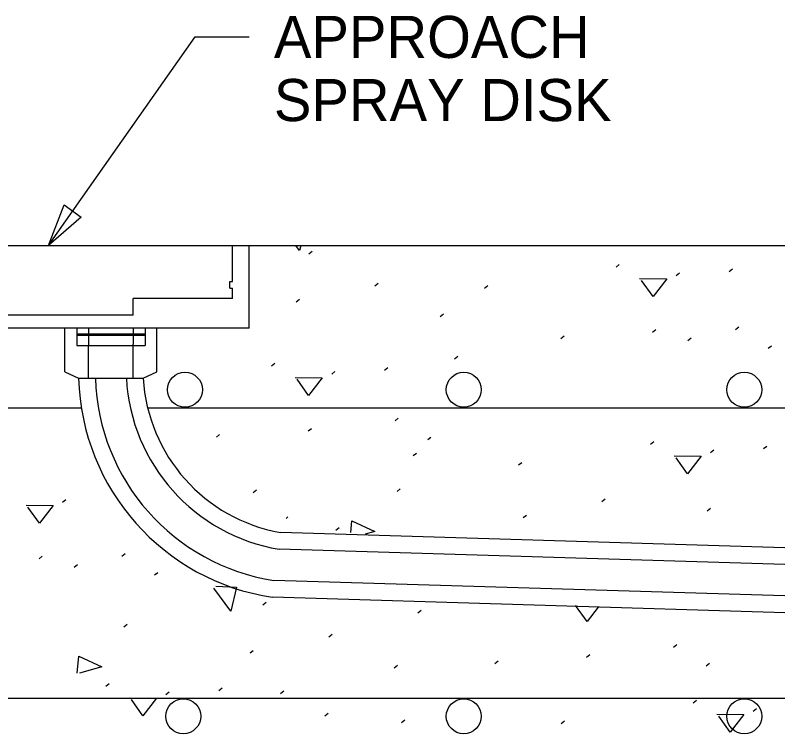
# Model space of a CAD drawing. Extents: x 3239 to 4230, y -4276 to -2494.
# Drawn here: x 3415.4 to 3469.7, y -3229.6 to -3178.4 of the extents above; entities that cross this region are included whole.
import ezdxf

# ---------------------------------------------------------------- set-up
doc = ezdxf.new("R2010")
doc.units = 0
doc.layers.add('2', color=7, linetype='Continuous')

msp = doc.modelspace()

# ---------------------------------------------------------------- linework, layer by layer
at = {"layer": '2'}
for p, q in [((3407.277, -3194.76), (3615.577, -3194.76)), ((3430.835, -3197.339), (3430.835, -3194.76)), ((3432.032, -3200.655), (3432.032, -3194.76)), ((3432.032, -3200.655), (3432.032, -3194.76)), ((3436.289, -3195.36), (3436.522, -3195.174)), ((3458.192, -3196.302), (3458.425, -3196.116)), ((3462.48, -3196.893), (3462.713, -3196.707)), ((3466.254, -3196.614), (3466.487, -3196.427)), ((3430.651, -3197.8), (3430.651, -3197.339)), ((3430.651, -3197.339), (3430.835, -3197.339)), ((3430.651, -3197.8), (3430.835, -3197.8)), ((3430.835, -3198.536), (3430.835, -3197.8)), ((3440.995, -3197.643), (3441.228, -3197.457)), ((3448.815, -3197.813), (3449.048, -3197.627)), ((3430.835, -3198.536), (3423.769, -3198.536)), ((3423.769, -3199.734), (3423.769, -3198.536)), ((3435.38, -3198.785), (3435.613, -3198.598)), ((3423.769, -3199.734), (3413.059, -3199.734)), ((3445.655, -3199.833), (3445.888, -3199.647)), ((3466.717, -3200.758), (3466.95, -3200.572)), ((3420.584, -3200.655), (3403.94, -3200.655)), ((3418.893, -3203.771), (3418.893, -3200.655)), ((3419.737, -3200.655), (3419.737, -3201.898)), ((3419.737, -3201.069), (3424.615, -3201.069)), ((3419.737, -3201.161), (3424.615, -3201.161)), ((3432.032, -3200.655), (3420.584, -3200.655)), ((3420.584, -3200.655), (3420.584, -3201.069)), ((3420.584, -3201.161), (3420.584, -3201.898)), ((3423.769, -3200.655), (3423.769, -3201.069)), ((3423.769, -3201.161), (3423.769, -3201.791)), ((3424.615, -3200.655), (3424.615, -3201.898)), ((3425.459, -3203.771), (3425.459, -3200.655)), ((3460.802, -3200.947), (3461.035, -3200.761)), ((3454.256, -3201.39), (3454.489, -3201.203)), ((3463.307, -3201.531), (3463.54, -3201.345)), ((3419.737, -3201.898), (3424.615, -3201.898)), ((3420.584, -3204.232), (3420.584, -3201.898)), ((3423.769, -3204.232), (3423.769, -3201.791)), ((3469.044, -3202.095), (3469.277, -3201.909)), ((3446.677, -3202.841), (3446.91, -3202.655)), ((3433.632, -3203.342), (3433.865, -3203.156)), ((3418.893, -3203.771), (3419.876, -3204.232)), ((3424.478, -3204.232), (3425.459, -3203.771)), ((3437.92, -3203.934), (3438.153, -3203.747)), ((3441.694, -3203.654), (3441.927, -3203.468)), ((3419.876, -3204.232), (3424.478, -3204.232)), ((3381.4, -3206.332), (3420.07, -3206.332)), ((3424.793, -3206.332), (3613.332, -3206.332)), ((3442.437, -3207.268), (3442.67, -3207.081)), ((3429.695, -3208.43), (3429.928, -3208.244)), ((3436.242, -3207.987), (3436.475, -3207.801)), ((3444.763, -3208.605), (3444.996, -3208.419)), ((3460.651, -3208.935), (3460.884, -3208.749)), ((3464.939, -3209.527), (3465.172, -3209.34)), ((3468.713, -3209.247), (3468.946, -3209.061)), ((3443.734, -3209.746), (3443.967, -3209.559)), ((3451.24, -3210.412), (3451.473, -3210.225)), ((3432.328, -3212.367), (3432.561, -3212.181)), ((3442.577, -3212.3), (3442.81, -3212.114)), ((3418.726, -3213.052), (3418.959, -3212.866)), ((3457.185, -3213.022), (3457.418, -3212.836)), ((3464.691, -3213.688), (3464.924, -3213.502)), ((3434.665, -3214.221), (3434.795, -3214.117)), ((3451.57, -3214.164), (3451.803, -3213.978)), ((3679.628, -3222.686), (3434.263, -3215.224)), ((3438.225, -3215.049), (3438.458, -3214.863)), ((3417.049, -3217.106), (3417.282, -3216.92)), ((3422.964, -3216.917), (3423.197, -3216.731)), ((3700.705, -3224.527), (3434.165, -3216.422)), ((3419.553, -3217.69), (3419.786, -3217.504)), ((3425.29, -3218.254), (3425.523, -3218.068)), ((3700.637, -3226.756), (3433.794, -3218.642)), ((3433.006, -3220.388), (3433.238, -3220.202)), ((3679.628, -3227.318), (3433.701, -3219.839)), ((3444.072, -3220.943), (3444.305, -3220.757)), ((3423.104, -3221.949), (3423.337, -3221.763)), ((3437.712, -3222.672), (3437.945, -3222.485)), ((3462.289, -3223.392), (3462.522, -3223.206)), ((3432.097, -3223.813), (3432.33, -3223.627)), ((3456.094, -3224.112), (3456.327, -3223.926)), ((3449.547, -3224.555), (3449.78, -3224.368)), ((3464.615, -3224.729), (3464.848, -3224.543)), ((3442.371, -3224.862), (3442.604, -3224.675)), ((3421.811, -3226.179), (3422.044, -3225.992)), ((3426.099, -3226.77), (3426.332, -3226.583)), ((3429.873, -3226.49), (3430.106, -3226.304)), ((3434.263, -3226.704), (3434.496, -3226.518)), ((3380.058, -3227.042), (3612.771, -3227.042)), ((3463.69, -3227.36), (3463.923, -3227.174)), ((3467.978, -3227.951), (3468.211, -3227.765)), ((3437.431, -3228.288), (3437.664, -3228.102)), ((3442.898, -3228.778), (3443.131, -3228.592)), ((3454.279, -3228.837), (3454.512, -3228.65))]:
    msp.add_line(p, q, dxfattribs=at)
for points in [[(3417.723, -3194.76), (3428.193, -3179.896), (3432.023, -3179.896)], [(3435.716, -3194.76), (3435.632, -3195.119), (3435.366, -3194.76)], [(3459.877, -3197.126), (3461.811, -3197.149), (3460.832, -3198.407), (3460.017, -3197.266)], [(3435.317, -3204.166), (3437.25, -3204.19), (3436.272, -3205.448), (3435.456, -3204.306)], [(3462.336, -3209.759), (3464.27, -3209.783), (3463.291, -3211.041), (3462.476, -3209.899)], [(3416.123, -3213.285), (3418.057, -3213.308), (3417.079, -3214.566), (3416.263, -3213.425)], [(3439.277, -3215.217), (3439.362, -3214.397), (3440.992, -3215.143), (3440.299, -3215.348)], [(3429.659, -3219.053), (3431.126, -3219.123), (3430.73, -3220.823), (3429.519, -3219.193)], [(3456.922, -3220.546), (3456.124, -3221.572), (3455.308, -3220.431)], [(3419.763, -3225.26), (3419.889, -3224.046), (3421.52, -3224.792), (3419.936, -3225.26)], [(3423.496, -3227.003), (3425.43, -3227.026), (3424.451, -3228.284), (3423.636, -3227.142)], [(3465.375, -3228.184), (3467.309, -3228.208), (3466.33, -3229.466), (3465.515, -3228.324)]]:
    msp.add_lwpolyline(points, dxfattribs=at)
msp.add_lwpolyline([(3420.064, -3192.739), (3417.723, -3194.76), (3418.837, -3191.876)], close=True, dxfattribs=at)
for centre in [(3427.454, -3205.049), (3447.337, -3205.049), (3467.337, -3205.049), (3427.337, -3228.325), (3447.337, -3228.325), (3467.337, -3228.325)]:
    msp.add_circle(centre, 1.247, dxfattribs=at)
for centre, radius, start, end in [((3436.094, -3203.793), 16.224, 181.5505, 261.5192), ((3436.094, -3203.793), 15.026, 181.6742, 261.1952), ((3436.338, -3203.526), 13.078, 183.0937, 260.4357), ((3436.338, -3203.526), 11.881, 183.4057, 259.9431)]:
    msp.add_arc(centre, radius, start, end, dxfattribs=at)

# ---------------------------------------------------------------- texts
for s, p in [('APPROACH', (3433.798, -3181.395)), ('SPRAY DISK', (3433.798, -3185.895))]:
    msp.add_text(s, height=3, dxfattribs=at).set_placement(p)

doc.saveas('drawing.dxf')
